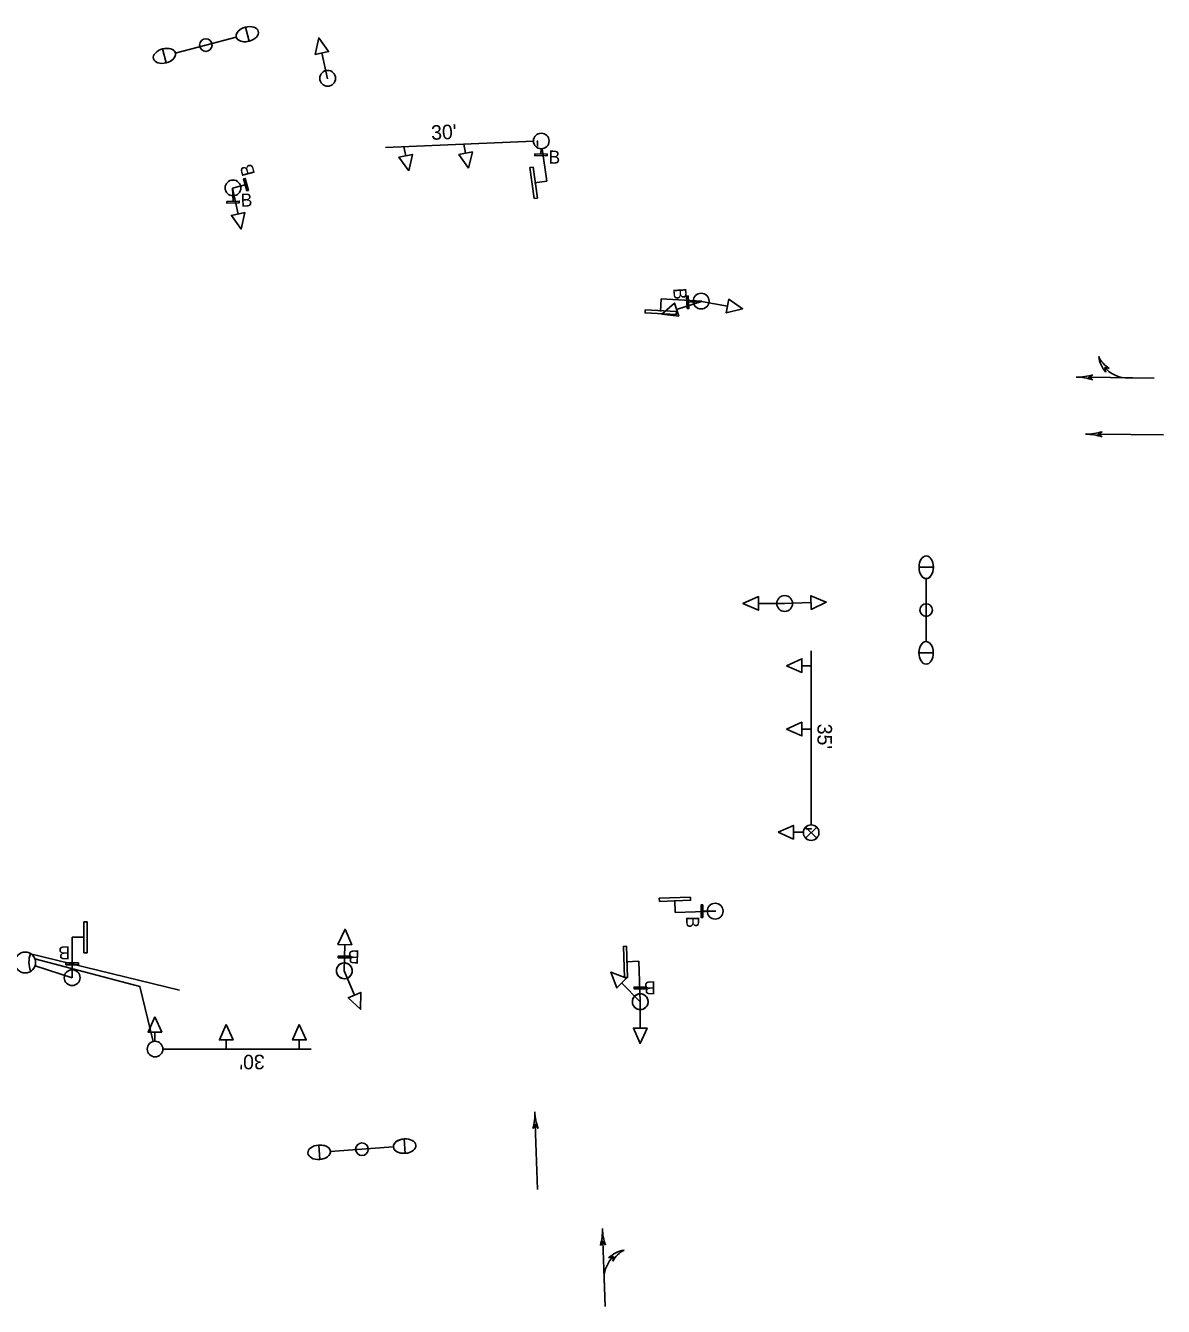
# Model space of a CAD drawing. Extents: x 596176 to 605330, y 332416 to 402398.
# Drawn here: x 605010.6 to 605229.4, y 349771.4 to 350017.8 of the extents above; entities that cross this region are included whole.
import ezdxf

# ---------------------------------------------------------------- set-up
doc = ezdxf.new("R2010")
doc.units = 0
for name, color, linetype in [('P_LTG', 7, 'Continuous'), ('P_SIG', 7, 'Continuous'), ('P_SIG_Bold', 7, 'Continuous'), ('P_SIG_Conduit', 7, 'Continuous')]:
    doc.layers.add(name, color=color, linetype=linetype)

# ---------------------------------------------------------------- blocks, each defined once
blk = doc.blocks.new('_U247')
at = {"layer": 'P_SIG_Bold'}
for p, q in [((-3.05, 0), (-0.11, 0)), ((-0.08, 0.08), (0.08, -0.08)), ((0.08, 0.08), (-0.08, -0.08))]:
    blk.add_line(p, q, dxfattribs=at)
blk.add_circle((0, 0), 0.114, dxfattribs=at)
blk.add_text("40'", height=0.213, dxfattribs=at).set_placement((-1.79, 0.09))

msp = doc.modelspace()

# ---------------------------------------------------------------- linework, layer by layer
at = {"layer": 'P_LTG'}
for p, q in [((605053.58, 350014.83), (605052.87, 350017.52)), ((605036.93, 350013.34), (605037.63, 350010.65)), ((605045.25, 350014.08), (605039.32, 350012.52)), ((605045.25, 350014.08), (605051.1, 350015.63)), ((605185.21, 349913.59), (605182.44, 349913.59)), ((605183.81, 349905.35), (605183.81, 349911.4)), ((605183.81, 349905.35), (605183.81, 349899.22)), ((605182.41, 349897.11), (605185.18, 349897.11)), ((605066.95, 349802.39), (605067.16, 349799.62)), ((605075.27, 349801.6), (605069.16, 349801.15)), ((605075.27, 349801.6), (605081.3, 349802.04)), ((605083.59, 349800.8), (605083.39, 349803.57))]:
    msp.add_line(p, q, dxfattribs=at)
for centre in [(605045.25, 350014.08), (605183.81, 349905.35), (605075.27, 349801.6)]:
    msp.add_circle(centre, 1.21, dxfattribs=at)
for centre, major_axis in [((605053.22, 350016.17), (2.11, 0.56)), ((605037.28, 350012), (-2.11, -0.56)), ((605183.82, 349913.59), (0, 2.18)), ((605183.8, 349897.11), (0, -2.18)), ((605067.05, 349801.01), (-2.17, -0.16)), ((605083.49, 349802.19), (2.17, 0.16))]:
    msp.add_ellipse(centre, major_axis=major_axis, ratio=0.636439, dxfattribs=at)
for centre, major_axis in [((605053.22, 350016.17), (2.11, 0.56)), ((605037.28, 350012), (-2.11, -0.56)), ((605183.82, 349913.59), (0, 2.18)), ((605183.8, 349897.11), (0, -2.18)), ((605067.05, 349801.01), (-2.17, -0.16)), ((605083.49, 349802.19), (2.17, 0.16))]:
    msp.add_ellipse(centre, major_axis=major_axis, ratio=0.636439, start_param=1.570796, end_param=4.712389, dxfattribs=at)
at = {"layer": 'P_SIG'}
for p, q in [((605067.58, 350012.56), (605068.62, 350007.61)), ((605083.7, 349992.78), (605083.36, 349994.52)), ((605095.22, 349993.27), (605094.88, 349995)), ((605109.73, 349994.13), (605109.71, 349993.12)), ((605110.85, 349987.9), (605109.97, 349994.14)), ((605050.4, 349986.52), (605052.81, 349987.17)), ((605051.44, 349981.57), (605050.4, 349986.52)), ((605050.4, 349986.52), (605050.47, 349984.02)), ((605110.85, 349987.9), (605108.48, 349987.56)), ((605132.85, 349965.24), (605132.71, 349962.84)), ((605132.85, 349965.24), (605140.63, 349964.81)), ((605135.8, 349963.19), (605140.61, 349964.74)), ((605140.61, 349964.74), (605138.12, 349964.6)), ((605145.59, 349963.85), (605140.61, 349964.74)), ((605219.04, 349951.86), (605218.15, 349952.05)), ((605218.38, 349951.11), (605218.15, 349952.05)), ((605227.65, 349949.97), (605215.08, 349950.15)), ((605227.65, 349949.97), (605222.06, 349950.05)), ((605229.44, 349939.06), (605216.87, 349939.18)), ((605151.53, 349906.64), (605156.58, 349906.62)), ((605161.64, 349906.79), (605156.59, 349906.62)), ((605159.92, 349894.65), (605161.69, 349894.65)), ((605159.92, 349882.45), (605161.69, 349882.45)), ((605158.27, 349862.59), (605160.04, 349862.59)), ((605135.53, 349847.13), (605135.44, 349849.53)), ((605135.53, 349847.13), (605143.32, 349847.4)), ((605143.33, 349847.4), (605140.83, 349847.4)), ((605019.53, 349842.41), (605021.93, 349842.41)), ((605019.53, 349842.41), (605019.53, 349834.61)), ((605071.98, 349840.98), (605071.88, 349835.93)), ((605019.53, 349834.61), (605019.53, 349837.11)), ((605073.84, 349831.26), (605071.87, 349835.92)), ((605073.84, 349831.27), (605071.88, 349835.93)), ((605128.53, 349837.77), (605126.13, 349837.69)), ((605128.53, 349837.77), (605128.81, 349829.98)), ((605125.24, 349833.57), (605128.81, 349829.98)), ((605128.79, 349824.92), (605128.81, 349829.98)), ((605035.44, 349824.14), (605035.44, 349822.36)), ((605049.17, 349822.64), (605049.17, 349820.86)), ((605063.23, 349822.64), (605063.23, 349820.86)), ((605109.06, 349793.83), (605108.62, 349806.39)), ((605122.05, 349771.35), (605121.61, 349783.92)), ((605122.73, 349780.67), (605123.66, 349780.95)), ((605123.51, 349780.05), (605123.66, 349780.95)), ((605122.05, 349771.35), (605121.86, 349776.94))]:
    msp.add_line(p, q, dxfattribs=at)
for points in [[(605066.97, 350015.46), (605068.87, 350012.84), (605066.29, 350012.29), (605066.97, 350015.46)], [(605068.87, 350012.84), (605066.97, 350015.46), (605066.29, 350012.29), (605068.87, 350012.84)], [(605066.97, 350015.46), (605068.87, 350012.84), (605066.29, 350012.29), (605066.97, 350015.46)], [(605052.05, 349978.67), (605050.15, 349981.3), (605052.73, 349981.84), (605052.05, 349978.67)], [(605050.15, 349981.3), (605052.05, 349978.67), (605052.73, 349981.84), (605050.15, 349981.3)], [(605052.05, 349978.67), (605050.15, 349981.3), (605052.73, 349981.84), (605052.05, 349978.67)], [(605132.98, 349962.28), (605135.39, 349964.44), (605136.21, 349961.94), (605132.98, 349962.28)], [(605135.39, 349964.44), (605132.98, 349962.28), (605136.21, 349961.94), (605135.39, 349964.44)], [(605132.98, 349962.28), (605135.39, 349964.44), (605136.21, 349961.94), (605132.98, 349962.28)], [(605148.51, 349963.34), (605145.36, 349962.56), (605145.82, 349965.15), (605148.51, 349963.34)], [(605145.36, 349962.56), (605148.51, 349963.34), (605145.82, 349965.15), (605145.36, 349962.56)], [(605148.51, 349963.34), (605145.36, 349962.56), (605145.82, 349965.15), (605148.51, 349963.34)], [(605215.89, 349950.64), (605215.08, 349950.15), (605215.87, 349949.64)], [(605217.67, 349939.67), (605216.87, 349939.18), (605217.66, 349938.67)], [(605148.57, 349906.64), (605151.53, 349907.95), (605151.53, 349905.32), (605148.57, 349906.64)], [(605151.53, 349907.95), (605148.57, 349906.64), (605151.53, 349905.32), (605151.53, 349907.95)], [(605148.57, 349906.64), (605151.53, 349907.95), (605151.53, 349905.32), (605148.57, 349906.64)], [(605164.6, 349906.89), (605161.69, 349905.47), (605161.6, 349908.11), (605164.6, 349906.89)], [(605161.69, 349905.47), (605164.6, 349906.89), (605161.6, 349908.11), (605161.69, 349905.47)], [(605164.6, 349906.89), (605161.69, 349905.47), (605161.6, 349908.11), (605164.6, 349906.89)], [(605072.03, 349843.94), (605073.3, 349840.96), (605070.66, 349841), (605072.03, 349843.94)], [(605073.3, 349840.96), (605072.03, 349843.94), (605070.66, 349841), (605073.3, 349840.96)], [(605072.03, 349843.94), (605073.3, 349840.96), (605070.66, 349841), (605072.03, 349843.94)], [(605123.15, 349835.66), (605126.17, 349834.5), (605124.31, 349832.63), (605123.15, 349835.66)], [(605126.17, 349834.5), (605123.15, 349835.66), (605124.31, 349832.63), (605126.17, 349834.5)], [(605123.15, 349835.66), (605126.17, 349834.5), (605124.31, 349832.63), (605123.15, 349835.66)], [(605074.99, 349828.54), (605072.63, 349830.75), (605075.05, 349831.78), (605074.99, 349828.54)], [(605075.01, 349828.54), (605072.63, 349830.74), (605075.06, 349831.78), (605075.01, 349828.54)], [(605072.63, 349830.74), (605075.01, 349828.54), (605075.06, 349831.78), (605072.63, 349830.74)], [(605075.01, 349828.54), (605072.63, 349830.74), (605075.06, 349831.78), (605075.01, 349828.54)], [(605128.79, 349821.96), (605127.48, 349824.92), (605130.11, 349824.92), (605128.79, 349821.96)], [(605127.48, 349824.92), (605128.79, 349821.96), (605130.11, 349824.92), (605127.48, 349824.92)], [(605128.79, 349821.96), (605127.48, 349824.92), (605130.11, 349824.92), (605128.79, 349821.96)], [(605109.14, 349805.61), (605108.62, 349806.39), (605108.15, 349805.57)], [(605122.14, 349783.14), (605121.61, 349783.92), (605121.14, 349783.1)]]:
    msp.add_lwpolyline(points, dxfattribs=at)
for points in [[(605095.79, 349990.36), (605093.93, 349993.01), (605096.52, 349993.52)], [(605084.27, 349989.88), (605082.4, 349992.53), (605084.99, 349993.04)], [(605108.51, 349993.15), (605110.91, 349993.1), (605110.9, 349992.77), (605108.5, 349992.82)], [(605109.02, 349984.65), (605108.19, 349990.6), (605107.59, 349990.51), (605108.43, 349984.57)], [(605053.12, 349986.01), (605052.5, 349988.33), (605052.82, 349988.41), (605053.44, 349986.09)], [(605049.27, 349983.99), (605051.67, 349984.05), (605051.67, 349983.73), (605049.27, 349983.66)], [(605138.05, 349965.8), (605138.18, 349963.4), (605137.86, 349963.39), (605137.72, 349965.78)], [(605129.77, 349963.14), (605135.76, 349962.81), (605135.73, 349962.21), (605129.73, 349962.54)], [(605156.96, 349894.65), (605159.92, 349895.97), (605159.92, 349893.34)], [(605156.96, 349882.45), (605159.92, 349883.77), (605159.92, 349881.13)], [(605155.32, 349862.59), (605158.27, 349863.91), (605158.27, 349861.27)], [(605132.49, 349849.29), (605138.49, 349849.5), (605138.47, 349850.1), (605132.47, 349849.89)], [(605140.83, 349848.6), (605140.83, 349846.2), (605140.5, 349846.2), (605140.5, 349848.6)], [(605021.79, 349845.37), (605021.79, 349839.37), (605022.39, 349839.37), (605022.39, 349845.37)], [(605073.13, 349838.4), (605070.73, 349838.45), (605070.73, 349838.77), (605073.13, 349838.73)], [(605126.16, 349840.65), (605126.38, 349834.65), (605125.78, 349834.63), (605125.57, 349840.63)], [(605020.73, 349837.11), (605018.33, 349837.11), (605018.33, 349837.44), (605020.73, 349837.44)], [(605130.02, 349832.47), (605127.62, 349832.48), (605127.62, 349832.81), (605130.02, 349832.8)], [(605035.44, 349827.09), (605036.76, 349824.14), (605034.13, 349824.14)], [(605049.17, 349825.59), (605050.49, 349822.64), (605047.86, 349822.64)], [(605063.23, 349825.59), (605064.55, 349822.64), (605061.92, 349822.64)]]:
    msp.add_lwpolyline(points, close=True, dxfattribs=at)
for centre, radius in [((605068.68, 350007.69), 1.52), ((605050.46, 349986.59), 1.52), ((605140.53, 349964.81), 1.52), ((605156.59, 349906.62), 1.52), ((605143.22, 349847.4), 1.52), ((605010.5, 349837.53), 2), ((605019.53, 349834.61), 1.52), ((605071.88, 349835.93), 1.52), ((605071.88, 349835.93), 1.52), ((605071.88, 349835.93), 1.52), ((605128.81, 349829.98), 1.52)]:
    msp.add_circle(centre, radius, dxfattribs=at)
for centre, radius, start, end in [((605068.68, 350007.69), 1.52, 90, 270), ((605068.68, 350007.69), 1.52, 270, 90), ((605050.46, 349986.59), 1.52, 90, 270), ((605050.46, 349986.59), 1.52, 270, 90), ((605140.53, 349964.81), 1.52, 90, 270), ((605140.53, 349964.81), 1.52, 270, 90), ((605221.68, 349956.27), 5.14, 204.4442, 239.0926), ((605223, 349955.04), 6.07, 188.4928, 220.349), ((605222.55, 349955.83), 5.8, 220.6483, 265.2122), ((605212.83, 349960.67), 10.49, 269.1775, 286.9398), ((605212.53, 349939.7), 10.49, 71.4152, 89.1775), ((605214.56, 349949.69), 10.49, 269.4824, 287.2447), ((605214.37, 349928.71), 10.49, 71.7201, 89.4824), ((605156.59, 349906.62), 1.52, 0, 180), ((605156.59, 349906.62), 1.52, 180, 0), ((605143.22, 349847.4), 1.52, 90, 270), ((605143.22, 349847.4), 1.52, 270, 90), ((605015.57, 349837.57), 4.36, 157.5751, 203.4282), ((605019.53, 349834.61), 1.52, 0, 180), ((605071.88, 349835.93), 1.52, 105, 285), ((605071.88, 349835.93), 1.52, 112.9907, 292.9907), ((605071.88, 349835.93), 1.52, 292.9907, 112.9907), ((605071.88, 349835.93), 1.52, 285, 105), ((605019.53, 349834.61), 1.52, 180, 0), ((605128.81, 349829.98), 1.52, 105, 285), ((605128.81, 349829.98), 1.52, 285, 105), ((605098.05, 349808.42), 10.49, 344.2404, 2.0027), ((605119.02, 349809.16), 10.49, 182.0027, 199.7651), ((605111.05, 349785.95), 10.49, 344.2404, 2.0027), ((605132.01, 349786.68), 10.49, 182.0027, 199.7651), ((605126.88, 349776.25), 6.07, 101.3181, 133.1742), ((605128.05, 349777.63), 5.14, 117.2694, 151.9179), ((605127.65, 349776.74), 5.8, 133.4736, 178.0375)]:
    msp.add_arc(centre, radius, start, end, dxfattribs=at)
at = {"layer": 'P_SIG_Bold'}
for p, q in [((605079.79, 349994.37), (605108.27, 349995.56)), ((605161.69, 349897.52), (605161.69, 349864.02)), ((605162.75, 349863.59), (605160.63, 349861.46)), ((605162.75, 349861.46), (605160.63, 349863.59)), ((605065.48, 349820.86), (605036.98, 349820.86))]:
    msp.add_line(p, q, dxfattribs=at)
for centre in [(605109.77, 349995.62), (605161.69, 349862.52), (605035.48, 349820.86)]:
    msp.add_circle(centre, 1.5, dxfattribs=at)
at = {"layer": 'P_SIG_Conduit'}
for points in [[(605040.18, 349832.19), (605011.54, 349839.23)], [(605035.12, 349822.32), (605032.55, 349832.94), (605012.37, 349838.23)], [(605019.53, 349834.61), (605012.4, 349836.91)]]:
    msp.add_lwpolyline(points, dxfattribs=at)

# ---------------------------------------------------------------- block references
at = {"layer": 'P_LTG', "yscale": 0.32808333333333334}
for p, xscale, rotation in [((605109.02, 349995.58), 0.32808333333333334, 92.2811652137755), ((605161.67, 349863.27), 0.3280833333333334, 0.0360180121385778)]:
    msp.add_blockref('_U247', p, dxfattribs=dict(at, xscale=xscale, rotation=rotation))

# ---------------------------------------------------------------- texts
at = {"layer": 'P_SIG'}
for rotation, p in [(358.7472, (605111.14, 349991.29)), (105.0395, (605054.73, 349989.25)), (1.5037, (605051.98, 349982.96)), (273.2261, (605135.15, 349967.27)), (270, (605137.64, 349846.42)), (180.015, (605019.11, 349840.65)), (178.8556, (605074.85, 349839.84)), (179.7615, (605131.78, 349833.91))]:
    msp.add_text('B', height=2.52, rotation=rotation, dxfattribs=at).set_placement(p)
at = {"layer": 'P_SIG_Bold'}
for s, rotation, p in [("30'", 2.3892, (605088.64, 349995.83)), ("35'", 270, (605162.9, 349883.48)), ("30'", 180, (605056.58, 349819.78))]:
    msp.add_text(s, height=2.8, rotation=rotation, dxfattribs=at).set_placement(p)

doc.saveas('drawing.dxf')
